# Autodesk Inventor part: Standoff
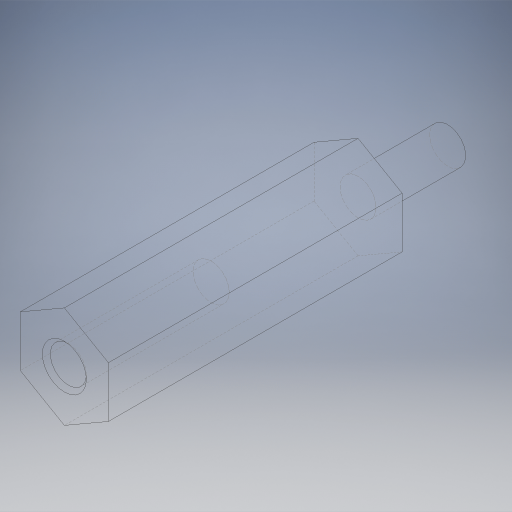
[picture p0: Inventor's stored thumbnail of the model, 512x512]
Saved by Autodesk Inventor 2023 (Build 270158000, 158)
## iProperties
Created: 2024-01
Part Number: Standoff
Material: Generic
Document SubType Name: Modeling
Designer: tornqvih
Density: 1 g/cm^3
Appearance: Default
Author: tornqvih
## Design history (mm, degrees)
sketch "Sketch1"
  geometry: L1 (3, -1.732)-(0, -3.464); L2 (0, -3.464)-(-3, -1.732); L3 (-3, -1.732)-(-3, 1.732); L4 (-3, 1.732)-(0, 3.464); L5 (0, 3.464)-(3, 1.732); L6 (3, 1.732)-(3, -1.732); 2 further points
  constraints: 12 end point, 1 coincident, 13 other
  dimensions: "d14" = 6 distance between parallel lines of L6 L3
extrude "Extrusion1" new body sketch "Sketch1" distance "d1" = 20; taper "d2" = 0 deg
sketch "Sketch2"
  geometry: 2 further points
  constraints: 1 coincident
hole "Hole1" sketch "Sketch2" at (0, 0) diameter "d3" = 2.459; stored, may be unused: countersink angle "d7" = 90 deg, drill point angle "d9" = 118 deg; dims "d4" = 8, "d5" = 3, "d6" = 2, "d8" = 10
sketch "Sketch3"
  geometry: C1 r 1.23 at (0, 0); 1 further point
  constraints: 1 centre point, 1 coincident
extrude "Extrusion2" join sketch "Sketch3" distance "d10" = 6.1; taper "d11" = 0 deg
thread "Thread1" dims "d12" = 30, "d13" = 0
body "Solid1"
